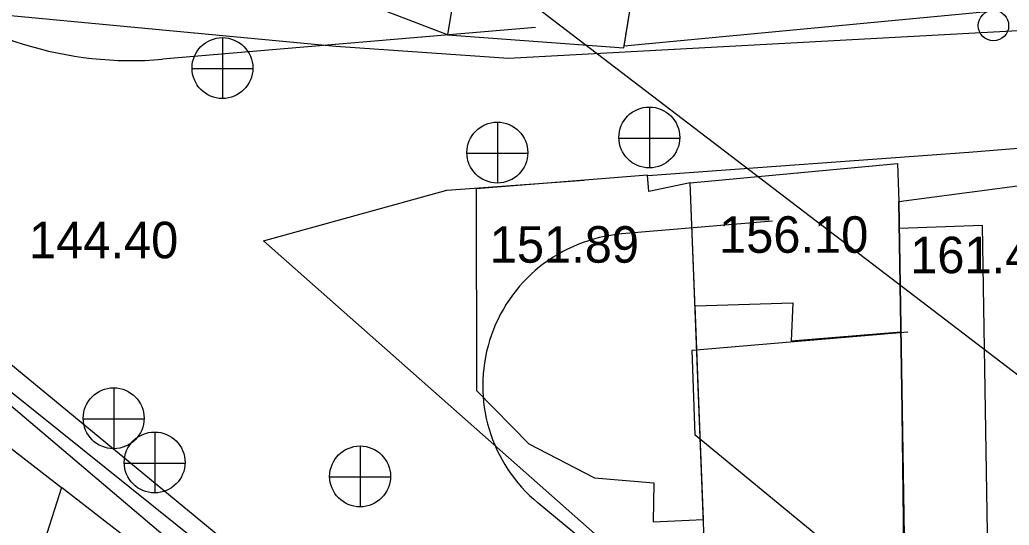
# Model space of a CAD drawing. Extents: x 419677 to 421689, y 4450851 to 4452923.
# Drawn here: x 420392.02 to 420424.55, y 4452078.82 to 4452095.43 of the extents above; entities that cross this region are included whole.
import ezdxf

# ---------------------------------------------------------------- set-up
doc = ezdxf.new("R2010")
doc.units = 0
for name, color, linetype in [('AA_HH', 7, 'Continuous'), ('Level 10', 7, 'Continuous'), ('Level 29', 7, 'Continuous'), ('Level 62', 7, 'Continuous'), ('Level 9', 7, 'Continuous')]:
    doc.layers.add(name, color=color, linetype=linetype)

msp = doc.modelspace()

# ---------------------------------------------------------------- linework, layer by layer
at = {"layer": 'AA_HH'}
for p, q in [((420398.697, 4452092.837), (420398.697, 4452094.837)), ((420397.677, 4452093.827), (420399.677, 4452093.827)), ((420412.729, 4452090.557), (420412.729, 4452092.557)), ((420407.734, 4452090.06), (420407.734, 4452092.06)), ((420411.709, 4452091.547), (420413.709, 4452091.547)), ((420406.714, 4452091.05), (420408.714, 4452091.05)), ((420395.122, 4452081.33), (420395.122, 4452083.33)), ((420394.102, 4452082.32), (420396.102, 4452082.32)), ((420396.468, 4452079.877), (420396.468, 4452081.877)), ((420403.222, 4452079.418), (420403.222, 4452081.418)), ((420395.448, 4452080.867), (420397.448, 4452080.867)), ((420402.202, 4452080.408), (420404.202, 4452080.408))]:
    msp.add_line(p, q, dxfattribs=at)
for points in [[(420317.236, 4452103.177), (420337.405, 4452116.594), (420344.369, 4452120.618), (420344.658, 4452120.664), (420379.054, 4452093.495), (420408.951, 4452068.147), (420424.16, 4452057.043), (420424.384, 4452056.89), (420424.576, 4452056.652), (420424.822, 4452056.326), (420423.72, 4452053.785)], [(420472.718, 4452100.465), (420471.167, 4452099.423), (420464.582, 4452098.677), (420443.424, 4452096.848), (420426.858, 4452095.176), (420408.081, 4452094.16), (420402.413, 4452094.559), (420391.601, 4452095.576), (420389.504, 4452096.627), (420385.679, 4452099.613), (420385.031, 4452100.473), (420384.774, 4452101.12), (420384.656, 4452102.321), (420385.298, 4452104.938)], [(420412.661, 4452090.31), (420423.219, 4452091.08), (420463.017, 4452094.314), (420476.345, 4452095.426), (420480.37, 4452095.808)], [(420433.878, 4452060.578), (420412.635, 4452077.028), (420400.032, 4452088.163), (420406.057, 4452089.829), (420410.576, 4452090.158)]]:
    msp.add_lwpolyline(points, dxfattribs=at)
for points in [[(420406.083, 4452094.938), (420400.295, 4452097.164), (420395.452, 4452099.416), (420393.51, 4452100.759), (420395.618, 4452111.087), (420395.618, 4452111.087), (420396.196, 4452113.335), (420398.672, 4452112.485), (420399.433, 4452115.583), (420409.141, 4452113.457)], [(420429.946, 4452096.282), (420411.883, 4452094.561), (420414.926, 4452113.266), (420419.385, 4452113.984), (420430.022, 4452115.404), (420430.104, 4452106.193)], [(420406.083, 4452094.938), (420411.875, 4452094.512), (420414.926, 4452113.266), (420409.232, 4452114.009)], [(420379.725, 4452090.659), (420393.388, 4452080.065), (420388.529, 4452064.834), (420379.952, 4452067.409)], [(420414.598, 4452076.388), (420414.058, 4452090.075), (420420.876, 4452090.71), (420420.913, 4452089.456), (420421.149, 4452075.039), (420420.913, 4452072.184)], [(420407.027, 4452089.877), (420407.03, 4452083.247), (420408.755, 4452081.493), (420410.91, 4452080.382), (420412.866, 4452080.217), (420412.838, 4452078.939), (420414.494, 4452079.006), (420414.058, 4452090.075), (420412.703, 4452089.789), (420412.66, 4452090.324)], [(420420.913, 4452089.456), (420426.889, 4452090.253), (420427.345, 4452072.134), (420425.853, 4452070.328), (420421.149, 4452075.039)], [(420423.671, 4452088.671), (420420.928, 4452088.577), (420421.149, 4452075.039), (420423.888, 4452075.205)], [(420414.217, 4452086.029), (420417.43, 4452086.13), (420417.382, 4452084.877), (420420.983, 4452085.174), (420421.111, 4452074.574), (420414.532, 4452078.042)], [(420405.557, 4452070.621), (420393.388, 4452080.065), (420388.529, 4452064.834), (420403.311, 4452060.104)]]:
    msp.add_lwpolyline(points, close=True, dxfattribs=at)
for centre, radius in [((420424.027, 4452095.241), 0.5), ((420398.682, 4452093.845), 1), ((420412.714, 4452091.565), 1), ((420407.719, 4452091.068), 1), ((420395.106, 4452082.338), 1), ((420396.453, 4452080.885), 1), ((420403.207, 4452080.427), 1)]:
    msp.add_circle(centre, radius, dxfattribs=at)
at = {"layer": 'Level 10'}
msp.add_lwpolyline([(420408.198, 4452069.984), (420345.402, 4452120.383), (420315.25, 4452102.126), (420310.494, 4452088.921)], dxfattribs=at)
at = {"layer": 'Level 29'}
msp.add_lwpolyline([(420460.864, 4452043.387), (420414.222, 4452081.778), (420414.123, 4452084.574), (420421.216, 4452085.177)], dxfattribs=at)
at = {"layer": 'Level 62'}
for p, q in [((420408.658, 4452070.167), (420355.096, 4452114.255)), ((420408.974, 4452095.177), (420396.716, 4452094.134)), ((420416.764, 4452088.814), (420411.815, 4452088.393)), ((420458.678, 4452038.71), (420409.061, 4452079.55))]:
    msp.add_line(p, q, dxfattribs=at)
for centre, radius, start, end in [((420395.699, 4452106.09), 12, 230.5434, 274.8631), ((420412.239, 4452083.411), 5, 94.8623, 230.5425)]:
    msp.add_arc(centre, radius, start, end, dxfattribs=at)
at = {"layer": 'Level 9'}
msp.add_lwpolyline([(420247.625, 4452233.749), (420254.875, 4452225.606), (420282.832, 4452200.893), (420395.898, 4452105.858), (420465.299, 4452052.876)], dxfattribs=at)

# ---------------------------------------------------------------- texts
at = {"layer": 'AA_HH'}
msp.add_text('144.40 ', height=1.2, rotation=0.0026, dxfattribs=at).set_placement((420392.322, 4452087.595))
for s, p in [('156.10', (420415.006, 4452087.775)), ('151.89', (420407.469, 4452087.45)), ('161.42', (420421.289, 4452087.104))]:
    msp.add_text(s, height=1.2, dxfattribs=at).set_placement(p)

doc.saveas('drawing.dxf')
